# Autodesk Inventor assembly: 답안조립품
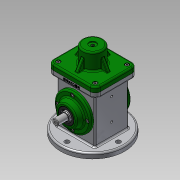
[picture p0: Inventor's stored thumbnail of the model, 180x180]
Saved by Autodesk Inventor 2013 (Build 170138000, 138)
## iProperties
Created: 2018-10
Part Number: 답안조립품
Document SubType Name: Assembly
Designer: Administrator
Author: Administrator
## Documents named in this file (14)
- C:\Documents and Settings\Administrator\바탕 화면\481007V1033\답안조립품.iam
- C:\Documents and Settings\Administrator\바탕 화면\481007V1033\본체.ipt
- C:\Documents and Settings\Administrator\바탕 화면\481007V1033\앞커버.ipt
- C:\Documents and Settings\Administrator\바탕 화면\481007V1033\볼트 M4 x 8.ipt
- C:\Documents and Settings\Administrator\바탕 화면\481007V1033\뒤커버.ipt
- C:\Documents and Settings\Administrator\바탕 화면\481007V1033\편심축.ipt
- C:\Documents and Settings\Administrator\바탕 화면\481007V1033\베어링 17 x 40 x 12.ipt
- C:\Documents and Settings\Administrator\바탕 화면\481007V1033\링크.ipt
- C:\Documents and Settings\Administrator\바탕 화면\481007V1033\슬라이더.ipt
- C:\Documents and Settings\Administrator\바탕 화면\481007V1033\클레비스 핀 6 x 22.ipt
- 클레비스 핀 6 x 22.ipt
- C:\Documents and Settings\Administrator\바탕 화면\481007V1033\덮개.ipt
- C:\Documents and Settings\Administrator\바탕 화면\481007V1033\E-링.ipt
- C:\Documents and Settings\Administrator\바탕 화면\481007V1033\오일 실 17 30 8.ipt
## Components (1 placed, 1 different names)
1. E-링:1
